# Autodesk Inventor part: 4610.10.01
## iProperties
Shininess: 64.0
Length Units: 11269
Angle Units: 11279
Time Units: 11290
Mass Units: 11283
Length Display Precision: 3
Angle Display Precision: 2
Compacted: True
Part Number: 4610.10.01
Document SubType Name: Modeling
Created: 2004-11
Material: 16MnCr5
Designer: sschwock
Manufacturer: Standard
Standards Organization: Custom
Description: Grundkörper
Density: 0.0
Volumn: 0.0
Area: 0.0
PropertySet Name: Model Information
Control State: 0
Master: False
Checked Out: False
Author: sschwock
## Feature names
1. 30mm Durchmesser [Extrusion]
2. 3,5mm Bohrung [Hole]
3. Extrusion4
4. Extrusion5
5. Extrusion6
6. Fase2 [Chamfer]
7. Fase3 [Chamfer]
8. Extrusion11
9. Extrusion12
